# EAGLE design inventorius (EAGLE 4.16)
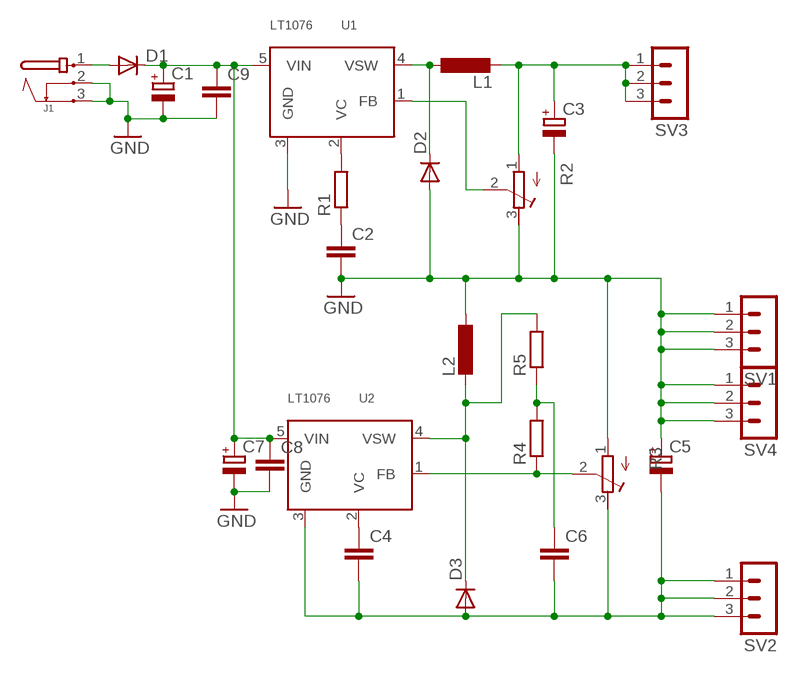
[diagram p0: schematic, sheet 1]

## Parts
C1  CPOL-EUE5-6  [E5-6]
C2  C-EU025-030X050  [C025-030X050]
C3  CPOL-EUE5-6  [E5-6]
C4  C-EU025-030X050  [C025-030X050]
C5  CPOL-EUE5-6  [E5-6]
C6  C-EU025-030X050  [C025-030X050]
C7  CPOL-EUE5-6  [E5-6]
C8  C-EU025-030X050  [C025-030X050]
C9  C-EU025-030X050  [C025-030X050]
D1  DIODE-SMC  [SMC]
D2  DIODE-SMB  [SMB]
D3  DIODE-SMB  [SMB]
J1  JACK-PMS  [JACK-PMS]
L1  L-EUTJ3-U1  [TJ3-U1]
L2  L-EUTJ3-U1  [TJ3-U1]
R1  R-EU_0204/2V  [0204V]
R2  R-TRIMM3339P  [RTRIM3339P]
R3  R-TRIMM3339P  [RTRIM3339P]
R4  R-EU_0207/7  [0207/7]
R5  R-EU_0207/7  [0207/7]
SV1  MA03-1  [MA03-1]
SV2  MA03-1  [MA03-1]
SV3  MA03-1  [MA03-1]
SV4  MA03-1  [MA03-1]
U1  LT1076  [TO-220-5]
U2  LT1076  [TO-220-5]

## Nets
GND: C1.- C2.2 C3.- C5.+ C7.- C8.2 C9.2 D2.A J1.2 J1.3 L2.1 R2.3(A) R3.1(E) SV1.1 SV1.2 SV1.3 SV4.1 SV4.2 SV4.3 U1.3(GND)
N$1: D1.A J1.1
N$2: C1.+ C7.+ C8.1 C9.1 D1.C U1.5(VIN) U2.5(VIN)
N$3: R1.2 U1.2(VC)
N$4: C2.1 R1.1
N$5: D2.C L1.1 U1.4(VSW)
N$8: C3.+ L1.2 R2.1(E) SV3.1 SV3.2 SV3.3
N$9: R2.2(S) U1.1(FB)
N$13: C4.1 U2.2(VC)
N$14: C4.2 C5.- C6.2 D3.A R3.3(A) SV2.1 SV2.2 SV2.3 U2.3(GND)
N$15: D3.C L2.2 R5.2 U2.4(VSW)
N$17: R3.2(S) R4.1 U2.1(FB)
N$21: C6.1 R4.2 R5.1

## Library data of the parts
C1 C3 C5 C7 = rcl:CPOL-EU: POLARIZED CAPACITOR, European symbol
C2 C4 C6 C8 C9 = rcl:C-EU: CAPACITOR, European symbol
D1-D3 = diode:DIODE-: DIODE
J1 = POWER-IN:JACK-PMS
L1 L2 = rcl:L-EU: INDUCTOR, European symbol
R1 R4 R5 = rcl:R-EU_: RESISTOR, European symbol
R2 R3 = rcl:R-TRIMM: Trimm resistor
SV1-SV4 = con-lstb:MA03-1: PIN HEADER
U1 U2 = LevoROMS:LT1076

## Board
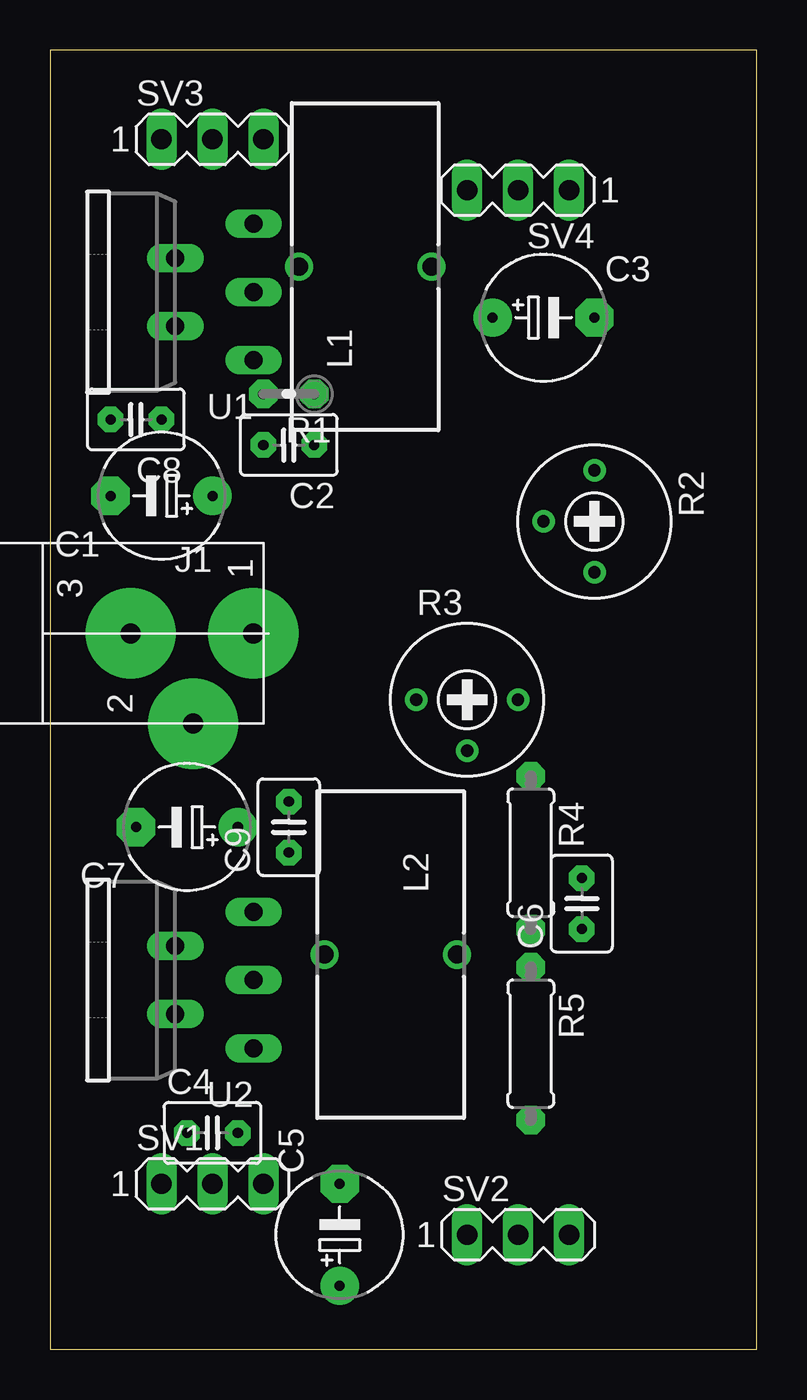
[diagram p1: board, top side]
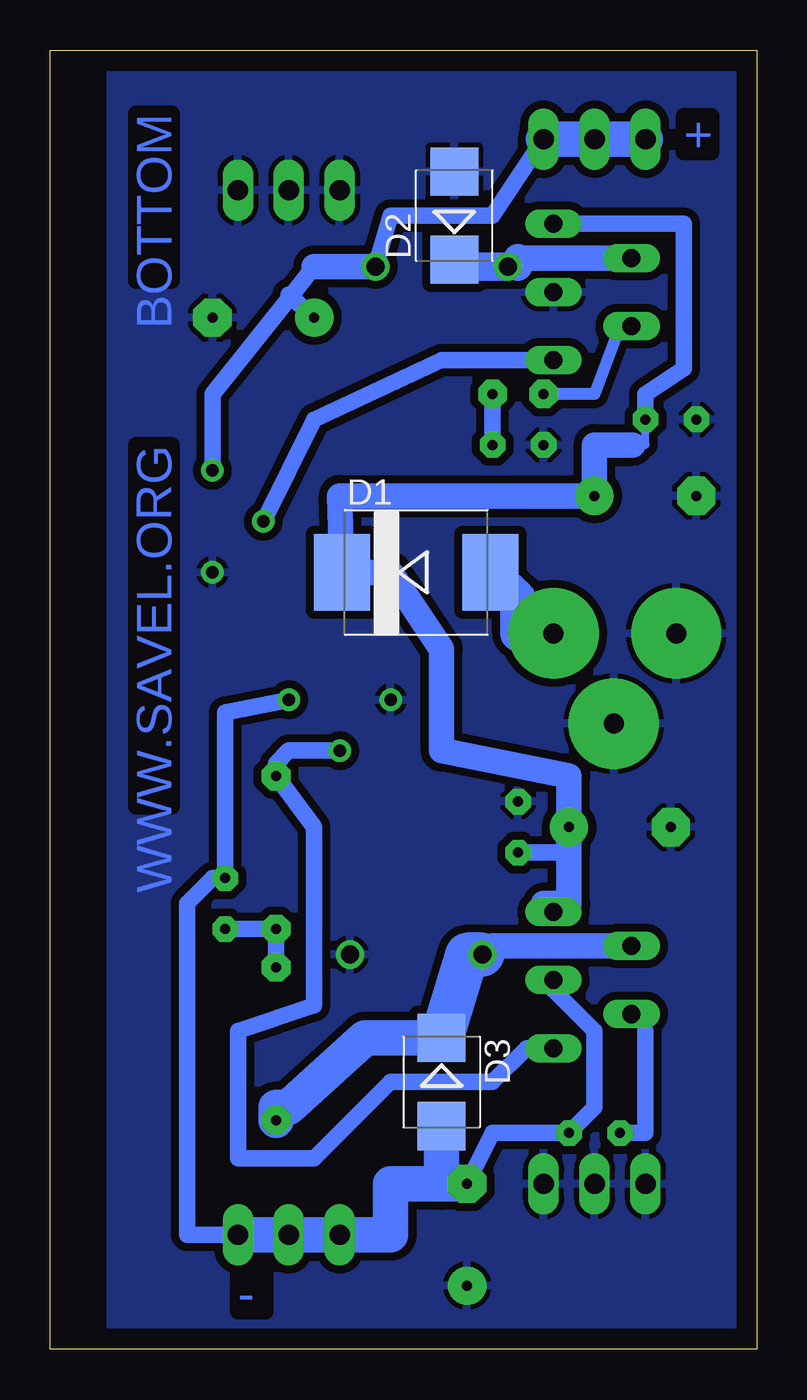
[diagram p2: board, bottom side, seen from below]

Size 35.23 x 64.76 mm. Coordinates in mm from the lower left corner, seen from the top.
Outline: 0,0 35.23,0 35.23,64.76 0,64.76 0,0
Copper layers (1*16): Top 0.035mm / dielectric 1.5mm / Bottom 0.035mm
Design rules "default": minimum track width 10mil, minimum drill 24mil, track to track 8mil, track to pad 8mil, pad to pad 8mil, via to via 8mil, smd to smd 8mil, copper to edge 40mil, drill to drill 8mil, minimum pad ring 10mil, minimum via ring 8mil, stop-mask expansion 4mil, vias tented up to drill 0mil, thermal gap 10mil

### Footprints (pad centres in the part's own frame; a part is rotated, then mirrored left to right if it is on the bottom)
E5-6 = drill 0.5 pad 1.905 round: + -2.54,0 | drill 0.5 pad 1.905 octagon: - 2.54,0
C025-030X050 = drill 0.5 pad 1.27 octagon: 1 -1.27,0; 2 1.27,0
SMC = smd 2.8 x 3.8: A 3.7,0; C -3.7,0
SMB = smd 2.4 x 2.4: A 2.2,0; C -2.2,0
JACK-PMS = drill 1 pad 4.5 round: 1 -0.5,-3.31; 2 -5,-0.31; 3 -0.5,2.809
TJ3-U1 = drill 0.9 round: 1 -3.3,0; 2 3.3,0
0204V = drill 0.5 pad 1.422 octagon: 1 -1.27,0; 2 1.27,0
RTRIM3339P = drill 0.61 round: 1 -2.54,0; 2 0,-2.54; 3 2.54,0
0207/7 = drill 0.5 pad 1.422 octagon: 1 -3.81,0; 2 3.81,0
MA03-1 = drill 1.016 long: 1 -2.54,0; 2 0,0; 3 2.54,0
TO-220-5 = drill 0.9 long: 1 -3.4,-2.05; 2 -1.7,1.85; 3 0,-2.05; 4 1.7,1.85; 5 3.4,-2.05

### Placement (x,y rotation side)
C1  5.55,42.54 180 top
C2  11.9,45.08 180 top
C3  24.6,51.43 0 top
C4  8.09,10.79 0 top
C5  14.44,5.71 90 top
C6  26.5,22.22 90 top
C7  6.82,26.03 180 top
C8  4.28,46.35 180 top
C9  11.9,26.03 90 top
D1  16.98,38.73 0 bottom
D2  15.08,56.51 90 bottom
D3  15.71,13.33 270 bottom
J1  6.82,36.19 90 top
L1  15.71,53.97 0 top
L2  16.98,19.68 180 top
R1  11.9,47.62 180 top
R2  27.14,41.27 270 top
R3  20.79,32.38 0 top
R4  23.96,24.76 270 top
R5  23.96,15.24 270 top
SV1  8.09,8.25 0 top
SV2  23.33,5.71 0 top
SV3  8.09,60.32 0 top
SV4  23.33,57.78 180 top
U1  8.09,52.7 90 top
U2  8.09,18.41 90 top

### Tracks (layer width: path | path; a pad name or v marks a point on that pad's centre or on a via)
GND
  pour Bottom (isolate 0.406): -0.8,64.13 -0.8,0.63 32.22,0.63 32.22,64.13
N$1
  Bottom 1.778: J1.1 11.9,35.69 11.9,37.46 D1.A
N$2
  Bottom 0.406: 6.19,45.08 5.55,45.08 C8.1
  Bottom 0.813: 9.36,24.76 C9.1 | U1.5 3.65,56.1 3.65,48.89 5.55,47.62 C8.1
  Bottom 1.27: 6.19,45.08 8.09,45.08 C1.+ 20.79,42.54 D1.C 18.25,38.73 15.71,34.92 15.71,29.84 9.36,28.57 C7.+ 9.36,24.76 9.36,22.22 10,22.22 | U2.5 10,21.81 10,22.22 | 10,22.22 10.63,22.22
N$3
  Bottom 0.61: U1.2 6.82,51 8.09,47.62 R1.2
N$4
  Bottom 0.813: C2.1 R1.1
N$5
  Bottom 0.406: L1.1 13.17,53.97 | 14.44,53.97 D2.C 15.71,53.97
  Bottom 0.813: 11.9,53.97 L1.1 | 14.44,53.97 15.71,53.97
  Bottom 1.27: U1.4 11.9,54.4
  Bottom 1.422: 11.9,54.4 11.9,53.97 | L1.1 14.44,53.97
N$8
  Bottom 0.406: 23.33,52.7 23.33,52.58 23.17,52.58
  Bottom 0.813: R2.1 27.14,47.62 23.17,52.58 22.06,53.97 | SV3.1 SV3.2 SV3.3 13.17,56.51 18.25,56.51 L1.2 | 23.33,52.58 C3.+
  Bottom 1.27: L1.2 22.06,53.97
  Bottom 1.778: SV3.1 SV3.3
N$9
  Bottom 0.813: U1.1 15.71,49.3 22.06,46.35 R2.2
N$13
  Bottom 0.254: 5.55,15.87 U2.2
  Bottom 0.813: C4.1 5.55,10.79 5.55,15.87
N$14
  Bottom 0.813: C5.- 13.17,10.79 C4.2 8.09,12.06 8.09,15.87 10.14,17.92 U2.3 | R3.3 26.5,31.74 C6.2 27.14,23.49 28.41,22.22 28.41,5.71 SV2.3
  Bottom 1.778: 15.71,8.25 D3.A | C5.- 15.71,8.25 | 15.71,8.25 18.25,8.25 18.25,5.71 SV2.3 SV2.2 SV2.1
N$15
  Bottom 1.27: U2.4 13.17,20.11 13.17,19.68 L2.2
  Bottom 1.778: D3.C 19.52,15.53 23.33,12.06 23.96,12.06 R5.2
  Bottom 2.184: D3.C 14.44,19.68 L2.2
N$17
  Bottom 0.813: R3.2 23.33,29.84 23.96,29.2 R4.1 22.06,26.03 22.06,17.14 25.87,15.87 25.87,9.52 22.06,9.52 18.25,13.33 13.17,13.33 11.49,15.01 U2.1
N$21
  Bottom 0.813: C6.1 R4.2 R5.1

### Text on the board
Bottom: BOTTOM | + | WWW.SAVEL.ORG | -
